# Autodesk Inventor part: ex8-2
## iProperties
Author: Administrator
Created: 2001-03
Part Number: ex8-2
Document SubType Name: Modeling
Designer: Administrator
Control State: 0
Master: False
Checked Out: False
PropertySet Name: Design Tracking Control
Shininess: 20.0
PropertySet Name: _Private Model Information
Density: 0.0
Volumn: 0.0
Area: 0.0
PropertySet Name: Model Information
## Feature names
1. Extrusion1
2. Extrusion2
